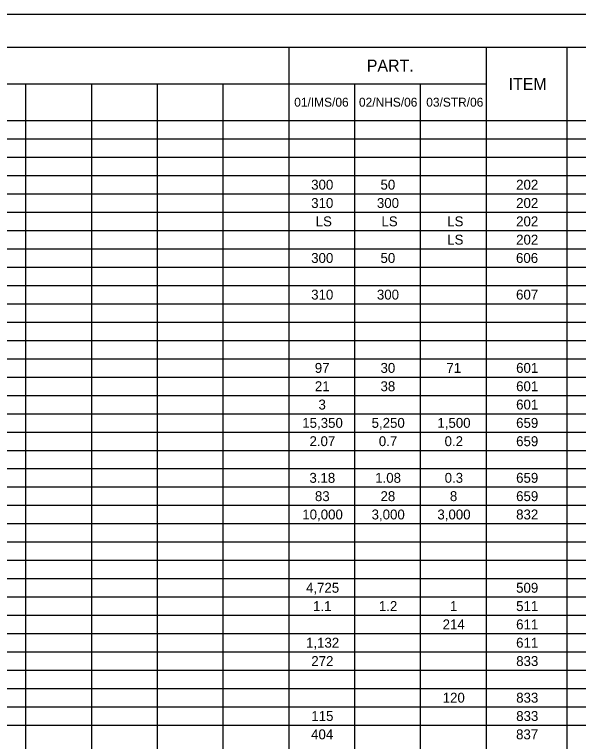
# Model space of a CAD drawing. Extents: x 0 to 34, y 0 to 22.
# Drawn here: x 8.36 to 16.98, y 10.89 to 22 of the extents above; entities that cross this region are included whole.
import ezdxf

# ---------------------------------------------------------------- set-up
doc = ezdxf.new("R2010")
doc.units = 0
for name, color, linetype in [('Default', 7, 'Continuous'), ('SH_Border', 7, 'Continuous'), ('SH_Cut_Line', 7, 'Continuous')]:
    doc.layers.add(name, color=color, linetype=linetype)

msp = doc.modelspace()

# ---------------------------------------------------------------- linework, layer by layer
at = {"layer": 'Default'}
for p, q in [((1.5, 21.5), (32.004, 21.5)), ((12.552, 21.5), (12.552, 0.5)), ((15.566, 21.5), (15.566, 0.5)), ((16.801, 21.5), (16.801, 0.5)), ((1.5, 20.94), (15.566, 20.94)), ((8.533, 20.94), (8.533, 0.5)), ((9.538, 20.94), (9.538, 0.5)), ((10.542, 20.94), (10.542, 0.5)), ((11.547, 20.94), (11.547, 0.5)), ((13.556, 20.94), (13.556, 0.5)), ((14.561, 20.94), (14.561, 0.5)), ((1.5, 20.38), (32.004, 20.38)), ((1.5, 20.1), (32.004, 20.1)), ((1.5, 19.82), (32.004, 19.82)), ((1.5, 19.54), (32.004, 19.54)), ((1.5, 19.26), (32.004, 19.26)), ((1.5, 18.98), (32.004, 18.98)), ((1.5, 18.7), (32.004, 18.7)), ((1.5, 18.42), (32.004, 18.42)), ((1.5, 18.14), (32.004, 18.14)), ((1.5, 17.86), (32.004, 17.86)), ((1.5, 17.58), (32.004, 17.58)), ((1.5, 17.3), (32.004, 17.3)), ((1.5, 17.02), (32.004, 17.02)), ((1.5, 16.74), (32.004, 16.74)), ((1.5, 16.46), (32.004, 16.46)), ((1.5, 16.18), (32.004, 16.18)), ((1.5, 15.9), (32.004, 15.9)), ((1.5, 15.62), (32.004, 15.62)), ((1.5, 15.34), (32.004, 15.34)), ((1.5, 15.06), (32.004, 15.06)), ((1.5, 14.78), (32.004, 14.78)), ((1.5, 14.5), (32.004, 14.5)), ((1.5, 14.22), (32.004, 14.22)), ((1.5, 13.94), (32.004, 13.94)), ((1.5, 13.66), (32.004, 13.66)), ((1.5, 13.38), (32.004, 13.38)), ((1.5, 13.1), (32.004, 13.1)), ((1.5, 12.82), (32.004, 12.82)), ((1.5, 12.54), (32.004, 12.54)), ((1.5, 12.26), (32.004, 12.26)), ((1.5, 11.98), (32.004, 11.98)), ((1.5, 11.7), (32.004, 11.7)), ((1.5, 11.42), (32.004, 11.42)), ((1.5, 11.14), (32.004, 11.14))]:
    msp.add_line(p, q, dxfattribs=at)
at = {"layer": 'SH_Border'}
msp.add_lwpolyline([(1.5, 21.5), (33.5, 21.5), (33.5, 0.5), (1.5, 0.5)], close=True, dxfattribs=at)
at = {"layer": 'SH_Cut_Line'}
msp.add_lwpolyline([(0, 0), (34, 0), (34, 22), (0, 22)], close=True, dxfattribs=at)

# ---------------------------------------------------------------- texts
at = {"layer": 'Default'}
for s, height, p in [('PART.', 0.1818, (13.745, 21.129)), ('ITEM', 0.1818, (15.912, 20.849)), ('01/IMS/06', 0.1364, (12.636, 20.592)), ('02/NHS/06', 0.1364, (13.625, 20.592)), ('03/STR/06', 0.1364, (14.653, 20.592)), ('300', 0.1515, (12.895, 19.324)), ('50', 0.1515, (13.954, 19.324)), ('202', 0.1515, (16.026, 19.324)), ('310', 0.1515, (12.895, 19.044)), ('300', 0.1515, (13.899, 19.044)), ('202', 0.1515, (16.026, 19.044)), ('LS', 0.1515, (12.964, 18.764)), ('LS', 0.1515, (13.968, 18.764)), ('LS', 0.1515, (14.973, 18.764)), ('202', 0.1515, (16.026, 18.764)), ('LS', 0.1515, (14.973, 18.484)), ('202', 0.1515, (16.026, 18.484)), ('300', 0.1515, (12.895, 18.204)), ('50', 0.1515, (13.954, 18.204)), ('606', 0.1515, (16.024, 18.204)), ('310', 0.1515, (12.895, 17.644)), ('300', 0.1515, (13.899, 17.644)), ('607', 0.1515, (16.025, 17.644)), ('97', 0.1515, (12.95, 16.524)), ('30', 0.1515, (13.954, 16.524)), ('71', 0.1515, (14.961, 16.524)), ('601', 0.1515, (16.026, 16.524)), ('21', 0.1515, (12.951, 16.244)), ('38', 0.1515, (13.954, 16.244)), ('601', 0.1515, (16.026, 16.244)), ('3', 0.152, (13.006, 15.964)), ('601', 0.1515, (16.026, 15.964)), ('15,350', 0.1515, (12.759, 15.684)), ('5,250', 0.1515, (13.818, 15.684)), ('1,500', 0.1515, (14.823, 15.684)), ('659', 0.1515, (16.026, 15.684)), ('2.07', 0.1515, (12.869, 15.404)), ('0.7', 0.1515, (13.928, 15.404)), ('0.2', 0.1515, (14.933, 15.404)), ('659', 0.1515, (16.026, 15.404)), ('3.18', 0.1515, (12.868, 14.844)), ('1.08', 0.1515, (13.873, 14.844)), ('0.3', 0.1515, (14.934, 14.844)), ('659', 0.1515, (16.026, 14.844)), ('83', 0.1515, (12.952, 14.564)), ('28', 0.1515, (13.954, 14.564)), ('8', 0.152, (15.014, 14.564)), ('659', 0.1515, (16.026, 14.564)), ('10,000', 0.1515, (12.759, 14.284)), ('3,000', 0.1515, (13.818, 14.284)), ('3,000', 0.1515, (14.823, 14.284)), ('832', 0.1515, (16.026, 14.284)), ('4,725', 0.1515, (12.816, 13.164)), ('509', 0.1515, (16.026, 13.164)), ('1.1', 0.1515, (12.924, 12.884)), ('1.2', 0.1515, (13.929, 12.884)), ('1', 0.152, (15.015, 12.884)), ('511', 0.1515, (16.026, 12.884)), ('214', 0.1515, (14.903, 12.604)), ('611', 0.1515, (16.026, 12.604)), ('1,132', 0.1515, (12.816, 12.324)), ('611', 0.1515, (16.026, 12.324)), ('272', 0.1515, (12.897, 12.044)), ('833', 0.1515, (16.027, 12.044)), ('120', 0.1515, (14.904, 11.484)), ('833', 0.1515, (16.027, 11.484)), ('115', 0.1515, (12.897, 11.204)), ('833', 0.1515, (16.027, 11.204)), ('404', 0.1515, (12.894, 10.924)), ('837', 0.1515, (16.025, 10.924))]:
    msp.add_text(s, height=height, dxfattribs=at).set_placement(p)

doc.saveas('drawing.dxf')
